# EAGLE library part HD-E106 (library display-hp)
LED DISPLAY + - 1/2 character, decimal point right
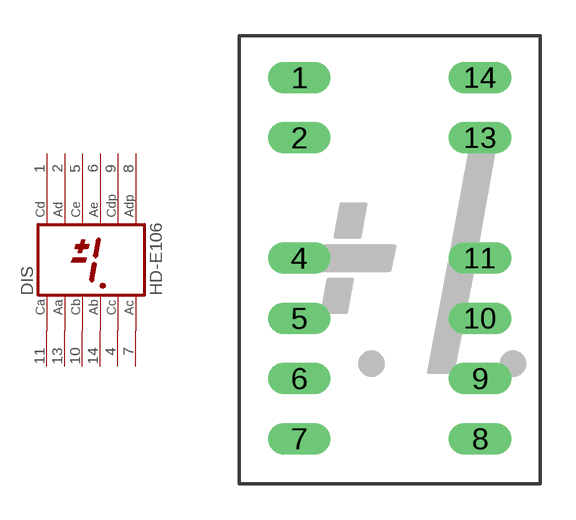
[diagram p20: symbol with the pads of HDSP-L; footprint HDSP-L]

Designator prefix DIS

## HD-E106 (OC_FARNELL: unknown; OC_NEWARK: unknown)  [HDSP-L]
1  CD  pas
2  AD  pas
4  CC  pas
5  CE  pas
6  AE  pas
7  AC  pas
8  ADP  pas
9  CDP  pas
10  CB  pas
11  CA  pas
13  AA  pas
14  AB  pas

## Footprint HDSP-L (pad centres in mm)
LED DISPLAY 12-mm + - 1/2 character, 2 decimal points
drill 0.813 long: 1 -3.81,7.62; 2 -3.81,5.08; 4 -3.81,0; 5 -3.81,-2.54; 6 -3.81,-5.08; 7 -3.81,-7.62; 8 3.81,-7.62; 9 3.81,-5.08; 10 3.81,-2.54; 11 3.81,0; 13 3.81,5.08; 14 3.81,7.62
